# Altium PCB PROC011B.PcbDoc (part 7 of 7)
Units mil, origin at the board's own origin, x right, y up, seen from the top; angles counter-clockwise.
Board outline 3304 x 2569 mil, 6 copper layers (TOP, L2-GND1, L3-GND/SIG, L4-GND/SIG, L5-GND2, BOTTOM), stack 55.77 mil thick; 376 components, 289 nets, 1284 pads, 1755 vias.
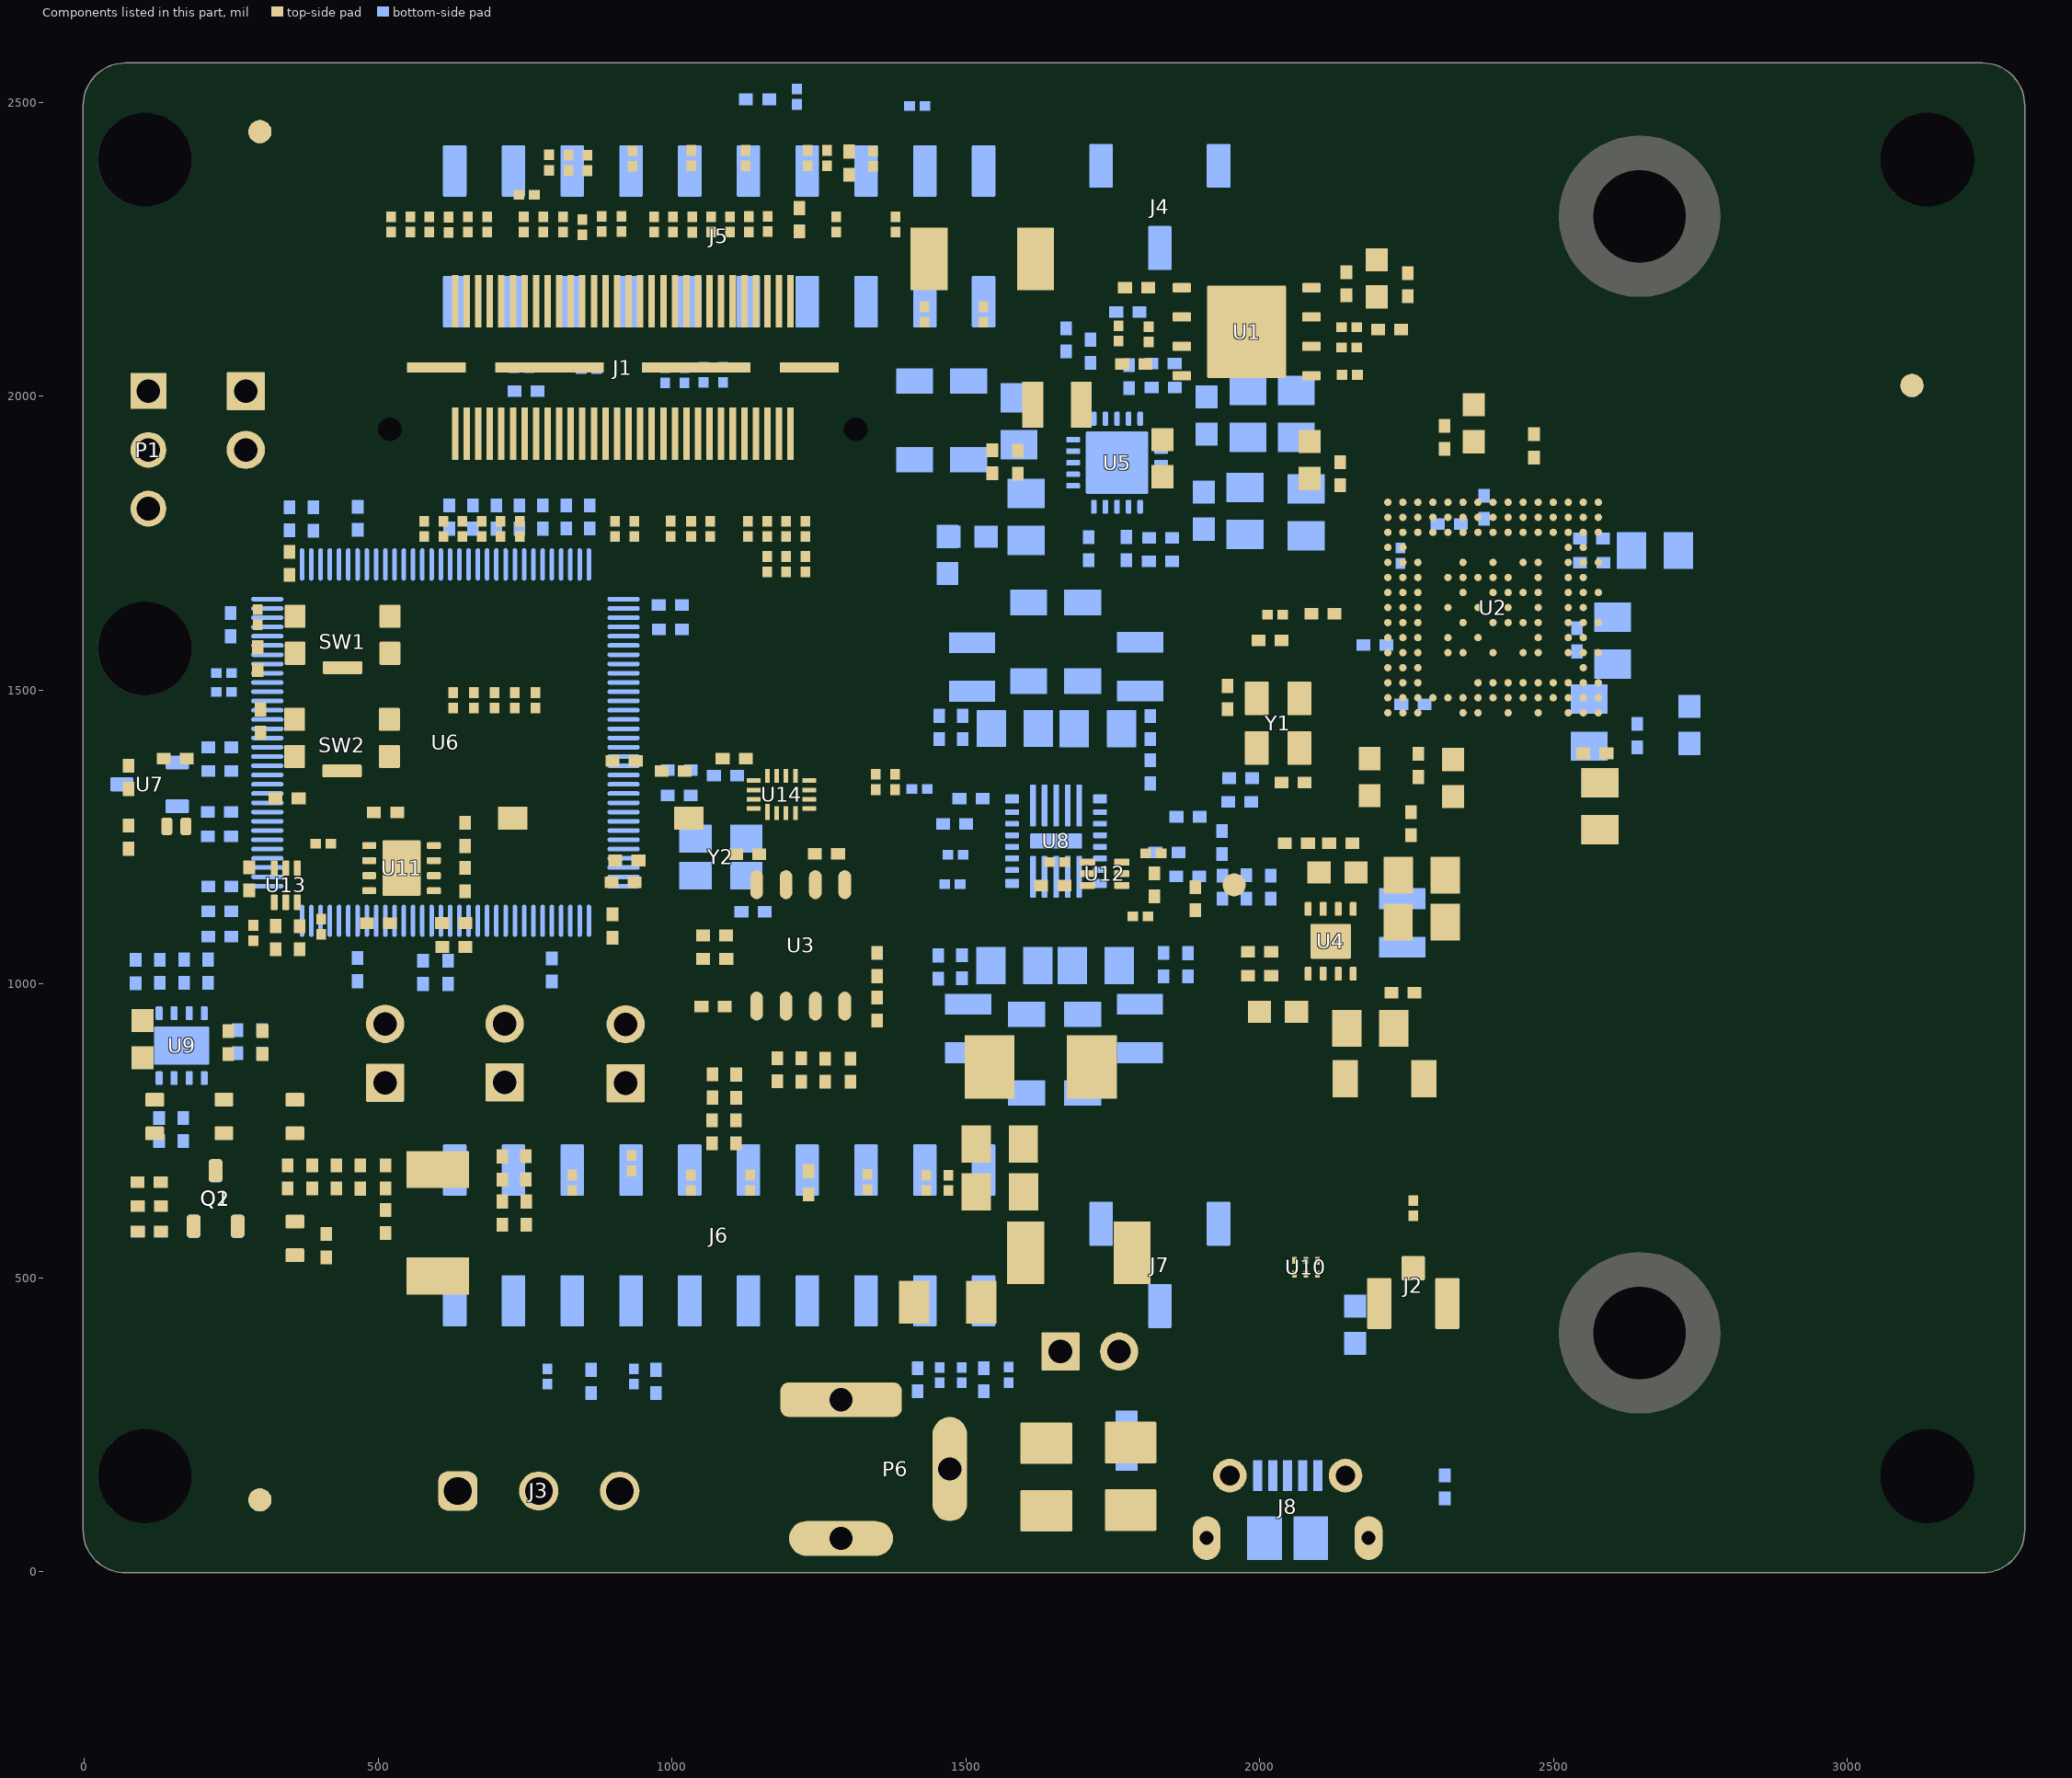
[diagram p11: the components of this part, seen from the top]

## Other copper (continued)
L4-GND/SIG:
  pour cut-out: 707.04,2233.8 707.04,2229.04 706.88,2228.89 707.03,2228.74 720.77,2228.74 720.77,2233.49 720.46,2233.8
  pour cut-out: 1164.04,659.3 1164.04,651.25 1166,649.29 1173.35,649.29 1176.16,652.1 1176.16,659.12 1174.68,660.6 1165.34,660.6
  pour cut-out: 1417.37,839.9 1417.1,839.88 1415.6,841.28 1415.48,841.41 1415.37,841.54 1415.27,841.68 1415.18,841.83 1415.11,841.99 1415.05,842.16 1415.01,842.33 1414.98,842.5 1414.96,842.67 1414.96,842.74 1414.96,1169.26 1414.97,1169.43 1414.99,1169.61 1415.03,1169.78 1415.08,1169.94 1415.15,1170.1 1415.23,1170.26 1415.33,1170.41 1415.43,1170.54 1415.55,1170.67 1415.68,1170.79 1415.82,1170.89 1415.97,1170.99 1417,1171.59 1417.15,1171.67 1417.32,1171.74 1417.48,1171.79 1417.65,1171.83 1417.82,1171.85 1418,1171.86 1418.17,1171.85 1418.35,1171.83 1418.52,1171.79 1418.68,1171.74 1418.84,1171.67 1418.9,1171.64 1419.27,1171.46 1419.27,1192.66 1419.28,1192.83 1419.3,1193.01 1419.34,1193.18 1419.39,1193.34 1419.46,1193.51 1419.54,1193.66 1419.63,1193.81 1419.74,1193.95 1419.86,1194.07 1419.98,1194.19 1420,1194.2 1422.74,1196.45 1423.6,1196.67 1424.05,1196.58 1424.05,1196.57 1425.56,1196.33 1425.84,1196.31 1426.01,1196.29 1426.18,1196.25 1426.35,1196.19 1426.51,1196.13 1426.66,1196.04 1426.81,1195.95 1426.95,1195.84 1427.08,1195.72 1427.19,1195.59 1427.3,1195.45 1427.39,1195.31 1427.47,1195.15 1427.53,1194.99 1427.59,1194.82 1427.62,1194.65 1427.64,1194.48 1427.65,1194.32 1427.65,825.7 1426.66,824.57 1425.91,824.47 1424.43,824.21 1424.19,824.16 1423.73,824.05 1422.85,824.24 1420.02,826.48 1419.89,826.59 1419.77,826.72 1419.66,826.86 1419.56,827 1419.48,827.15 1419.41,827.31 1419.35,827.48 1419.31,827.65 1419.28,827.82 1419.27,827.99 1419.27,828.05 1419.27,842.69 1419.26,842.52 1419.24,842.34 1419.2,842.17 1419.15,842.01 1419.08,841.85 1419,841.69 1418.9,841.54 1418.8,841.41 1418.72,841.32 1417.37,839.9
  pour cut-out: 1421.27,633.02 1421.27,633.01 1421.1,633.02 1420.92,633.04 1420.75,633.08 1420.59,633.13 1420.42,633.2 1420.27,633.28 1420.12,633.37 1419.98,633.48 1419.86,633.6 1419.74,633.72 1419.63,633.86 1419.54,634.01 1419.46,634.16 1419.39,634.33 1419.34,634.49 1419.3,634.66 1419.28,634.84 1419.27,635.01 1419.27,786.75 1419.28,786.92 1419.3,787.1 1419.34,787.27 1419.39,787.43 1419.45,787.6 1419.53,787.75 1419.63,787.9 1419.73,788.04 1419.85,788.17 1419.98,788.29 1420.02,788.32 1422.85,790.56 1423.73,790.75 1424.19,790.64 1425.67,790.36 1425.91,790.33 1426.66,790.23 1427.65,789.1 1427.65,660.69 1427.66,660.52 1427.68,660.34 1427.72,660.17 1427.77,660.01 1427.84,659.84 1427.92,659.69 1428.01,659.54 1428.12,659.4 1428.24,659.28 1428.24,659.27 1451.09,636.43 1451.21,636.3 1451.31,636.16 1451.41,636.01 1451.49,635.86 1451.55,635.7 1451.6,635.53 1451.64,635.36 1451.66,635.19 1451.67,635.01 1451.66,634.84 1451.64,634.67 1451.6,634.5 1451.55,634.33 1451.52,634.25 1451.29,633.68 1450.29,633.02 1421.27,633.02
  pour cut-out: 2548.83,2011.37 2547.8,2011.32 2547.33,2011.56 2545.96,2012.18 2544.54,2012.68 2543.09,2013.05 2541.61,2013.3 2540.11,2013.41 2538.61,2013.39 2537.11,2013.25 2535.63,2012.97 2535.07,2012.83 2534.55,2012.69 2533.53,2012.96 2509.05,2037.43 2508.93,2037.56 2508.83,2037.7 2508.73,2037.85 2508.65,2038 2508.59,2038.16 2508.54,2038.33 2508.5,2038.5 2508.48,2038.67 2508.47,2038.85 2508.47,2101.5 2508.48,2101.67 2508.5,2101.85 2508.54,2102.02 2508.59,2102.18 2508.66,2102.34 2508.74,2102.5 2508.84,2102.65 2508.94,2102.78 2509.06,2102.91 2509.19,2103.03 2509.33,2103.13 2509.48,2103.23 2509.63,2103.31 2509.7,2103.34 2510.27,2103.57 2511.44,2103.34 2552.55,2062.23 2552.67,2062.1 2552.77,2061.96 2552.87,2061.81 2552.95,2061.66 2553.01,2061.5 2553.06,2061.33 2553.1,2061.16 2553.12,2060.99 2553.13,2060.82 2553.13,2015.13 2553.12,2014.96 2553.1,2014.78 2553.06,2014.61 2553.01,2014.45 2552.94,2014.28 2552.86,2014.13 2552.77,2013.98 2552.66,2013.84 2552.54,2013.72 2552.42,2013.6 2552.28,2013.49 2552.18,2013.43 2548.83,2011.37
  pour cut-out: 2552.18,1978.97 2552.33,1978.87 2552.46,1978.76 2552.59,1978.64 2552.7,1978.51 2552.8,1978.37 2552.89,1978.22 2552.97,1978.06 2553.03,1977.9 2553.08,1977.73 2553.11,1977.56 2553.13,1977.39 2553.13,1977.27 2553.13,1936.26 2553.12,1936.09 2553.1,1935.91 2553.06,1935.74 2553.01,1935.58 2552.94,1935.41 2552.86,1935.26 2552.77,1935.11 2552.66,1934.97 2552.54,1934.85 2552.42,1934.73 2552.39,1934.71 2549.63,1932.47 2548.75,1932.25 2548.31,1932.35 2546.83,1932.6 2545.33,1932.71 2543.83,1932.69 2542.33,1932.55 2540.86,1932.27 2539.41,1931.87 2538.27,1931.45 2537.8,1931.26 2536.82,1931.37 2533.65,1933.5 2533.51,1933.61 2533.38,1933.72 2533.26,1933.85 2533.15,1933.98 2533.06,1934.13 2532.97,1934.28 2532.9,1934.44 2532.85,1934.61 2532.81,1934.78 2532.78,1934.95 2532.77,1935.13 2532.77,1935.15 2532.77,1975.16 2532.78,1975.33 2532.8,1975.51 2532.84,1975.68 2532.89,1975.84 2532.95,1976.01 2533.03,1976.16 2533.13,1976.31 2533.23,1976.45 2533.35,1976.58 2533.45,1976.67 2536.04,1978.94 2536.86,1979.19 2537.29,1979.13 2538.79,1979 2540.29,1979 2541.79,1979.13 2543.26,1979.39 2544.72,1979.77 2546.13,1980.29 2547.33,1980.84 2547.8,1981.08 2548.83,1981.03 2552.18,1978.97
  pour cut-out: 1735.73,1667.3 1735.73,1581.11 1735.74,1580.94 1735.76,1580.76 1735.8,1580.59 1735.85,1580.43 1735.92,1580.26 1736,1580.11 1736.09,1579.96 1736.2,1579.82 1736.32,1579.7 1736.32,1579.69 1755.09,1560.93 1755.21,1560.8 1755.31,1560.66 1755.41,1560.51 1755.49,1560.36 1755.55,1560.2 1755.6,1560.03 1755.64,1559.86 1755.66,1559.69 1755.67,1559.51 1755.66,1559.34 1755.64,1559.17 1755.6,1559 1755.55,1558.83 1755.52,1558.75 1755.29,1558.18 1754.29,1557.52 1626.56,1557.52 1626.39,1557.53 1626.21,1557.55 1626.04,1557.59 1625.88,1557.64 1625.71,1557.71 1625.56,1557.79 1625.41,1557.88 1625.27,1557.99 1625.15,1558.11 1625.03,1558.23 1624.92,1558.37 1624.83,1558.52 1624.75,1558.67 1624.72,1558.75 1624.48,1559.32 1624.72,1560.49 1732.32,1668.1 1732.45,1668.22 1732.59,1668.32 1732.74,1668.42 1732.89,1668.5 1733.05,1668.56 1733.22,1668.61 1733.39,1668.65 1733.56,1668.67 1733.74,1668.68 1733.91,1668.67 1734.08,1668.65 1734.25,1668.61 1734.42,1668.56 1734.5,1668.53 1735.07,1668.29 1735.73,1667.3
  pour cut-out: 1500.85,1793.15 1501.01,1793.08 1501.16,1792.99 1501.3,1792.88 1501.43,1792.77 1501.55,1792.64 1501.66,1792.51 1501.76,1792.36 1501.84,1792.21 1501.91,1792.05 1501.97,1791.88 1502.01,1791.71 1502.04,1791.54 1502.05,1791.37 1502.05,1791.32 1502.05,1728.61 1502.04,1728.44 1502.02,1728.26 1501.98,1728.09 1501.93,1727.93 1501.86,1727.76 1501.78,1727.61 1501.69,1727.46 1501.58,1727.32 1501.46,1727.2 1501.46,1727.19 1480.93,1706.66 1480.8,1706.54 1480.66,1706.44 1480.51,1706.34 1480.36,1706.26 1480.2,1706.2 1480.03,1706.15 1479.86,1706.11 1479.69,1706.09 1479.51,1706.08 1479.34,1706.09 1479.17,1706.11 1479,1706.15 1478.83,1706.2 1478.75,1706.23 1478.18,1706.46 1477.51,1707.46 1477.51,1785.9 1477.52,1786.07 1477.54,1786.25 1477.58,1786.42 1477.63,1786.58 1477.7,1786.75 1477.78,1786.9 1477.87,1787.05 1477.98,1787.19 1478.1,1787.31 1478.18,1787.39 1480.71,1789.66 1481.51,1789.92 1481.94,1789.88 1483.44,1789.78 1484.94,1789.82 1486.43,1789.99 1487.91,1790.29 1489.35,1790.71 1490.75,1791.26 1492.09,1791.93 1493.37,1792.71 1494.58,1793.6 1495.35,1794.27 1495.8,1794.68 1496.95,1794.87 1500.85,1793.15
  pour cut-out: 1132.48,2240.73 1131.78,2239.97 1131.29,2239.8 1129.89,2239.25 1128.55,2238.58 1127.26,2237.8 1126.05,2236.91 1124.92,2235.92 1123.89,2234.83 1122.95,2233.66 1122.12,2232.41 1121.39,2231.09 1120.79,2229.72 1120.31,2228.29 1119.96,2226.83 1119.73,2225.35 1119.63,2223.85 1119.67,2222.35 1119.83,2220.86 1120.13,2219.38 1120.55,2217.94 1121.1,2216.54 1121.76,2215.2 1122.55,2213.91 1123.44,2212.7 1124.43,2211.57 1125.52,2210.54 1126.69,2209.6 1127.94,2208.77 1129.26,2208.04 1130.63,2207.44 1132.06,2206.96 1133.52,2206.61 1135,2206.38 1136.5,2206.28 1138,2206.32 1139.49,2206.48 1140.97,2206.78 1142.41,2207.2 1143.81,2207.75 1145.15,2208.42 1146.44,2209.2 1147.65,2210.09 1148.78,2211.08 1149.81,2212.17 1150.75,2213.34 1151.58,2214.59 1152.31,2215.91 1152.91,2217.28 1153.15,2217.94 1153.32,2218.43 1154.08,2219.13 1157.89,2220.01 1158.06,2220.04 1158.24,2220.06 1158.41,2220.06 1158.58,2220.05 1158.76,2220.02 1158.93,2219.98 1159.09,2219.92 1159.25,2219.85 1159.4,2219.76 1159.55,2219.66 1159.68,2219.55 1159.76,2219.48 1174.71,2204.53 1174.83,2204.4 1174.93,2204.26 1175.03,2204.12 1175.11,2203.96 1175.18,2203.8 1175.23,2203.63 1175.27,2203.46 1175.29,2203.29 1175.3,2203.12 1175.29,2202.94 1175.27,2202.77 1175.23,2202.6 1175.18,2202.43 1175.15,2202.35 1174.91,2201.78 1173.92,2201.12 1088.25,2201.12 1088.08,2201.13 1087.9,2201.15 1087.73,2201.19 1087.57,2201.24 1087.41,2201.31 1087.25,2201.39 1087.1,2201.49 1086.97,2201.59 1086.84,2201.71 1086.72,2201.84 1086.62,2201.98 1086.52,2202.13 1086.44,2202.28 1086.41,2202.35 1086.18,2202.92 1086.41,2204.09 1124.53,2242.22 1125.56,2243.35 1126.49,2244.56 1127.32,2245.84 1128.02,2247.2 1128.09,2247.33 1128.24,2247.66 1128.49,2247.92 1128.62,2248.04 1128.76,2248.14 1128.9,2248.24 1129.06,2248.32 1129.22,2248.39 1129.39,2248.44 1129.56,2248.48 1129.73,2248.5 1129.9,2248.51 1130.08,2248.5 1130.25,2248.48 1130.42,2248.44 1130.59,2248.39 1130.75,2248.33 1130.9,2248.25 1131.05,2248.15 1131.19,2248.05 1131.32,2247.93 1131.32,2247.92 1132.83,2246.41 1132.95,2246.28 1133.05,2246.14 1133.15,2245.99 1133.23,2245.84 1133.29,2245.68 1133.34,2245.51 1133.38,2245.34 1133.4,2245.17 1133.41,2244.99 1133.4,2244.82 1133.38,2244.65 1133.36,2244.54 1132.48,2240.73
  pour cut-out: 1046.07,2214.12 927.55,2214.12 927.38,2214.13 927.2,2214.15 927.03,2214.19 926.87,2214.24 926.71,2214.31 926.55,2214.39 926.4,2214.49 926.27,2214.59 926.14,2214.71 926.02,2214.84 925.92,2214.98 925.82,2215.13 925.74,2215.28 925.71,2215.35 925.48,2215.92 925.71,2217.09 971.72,2263.1 971.85,2263.22 971.99,2263.32 972.14,2263.42 972.29,2263.5 972.45,2263.56 972.62,2263.61 972.79,2263.65 972.96,2263.67 973.13,2263.68 1051.78,2263.68 1051.95,2263.67 1052.13,2263.65 1052.3,2263.61 1052.46,2263.56 1052.63,2263.5 1052.78,2263.42 1052.93,2263.32 1053.07,2263.22 1053.2,2263.1 1053.32,2262.97 1053.42,2262.84 1055.58,2259.76 1055.71,2258.79 1055.55,2258.33 1055.1,2256.9 1054.78,2255.43 1054.59,2253.94 1054.53,2252.44 1054.6,2250.94 1054.8,2249.45 1055.13,2247.98 1055.59,2246.55 1056.17,2245.17 1056.87,2243.84 1057.68,2242.57 1058.6,2241.38 1059.62,2240.28 1060.73,2239.27 1061.92,2238.36 1063.19,2237.56 1063.6,2237.32 1064.12,2236.55 1064.6,2232.93 1064.62,2232.76 1064.62,2232.58 1064.6,2232.41 1064.57,2232.24 1064.53,2232.07 1064.47,2231.9 1064.39,2231.75 1064.31,2231.59 1064.21,2231.45 1064.09,2231.32 1064.04,2231.26 1047.48,2214.7 1047.35,2214.58 1047.21,2214.48 1047.06,2214.38 1046.91,2214.3 1046.75,2214.24 1046.58,2214.19 1046.41,2214.15 1046.24,2214.13 1046.07,2214.12
  pour cut-out: 1393.52,1312.55 1392.95,1312.31 1391.77,1312.55 1389.85,1314.47 1389.73,1314.6 1389.63,1314.74 1389.53,1314.89 1389.45,1315.04 1389.39,1315.2 1389.34,1315.37 1389.3,1315.54 1389.28,1315.71 1389.27,1315.88 1389.27,1451.36 1389.28,1451.53 1389.3,1451.71 1389.34,1451.88 1389.39,1452.04 1389.46,1452.21 1389.54,1452.36 1389.63,1452.51 1389.74,1452.65 1389.86,1452.77 1389.98,1452.89 1390.12,1453 1390.27,1453.09 1390.42,1453.17 1390.59,1453.24 1390.75,1453.29 1390.84,1453.31 1391.56,1453.47 1391.56,1453.46 1391.73,1453.49 1391.91,1453.51 1392.08,1453.51 1392.26,1453.49 1392.43,1453.46 1392.6,1453.42 1392.76,1453.36 1392.92,1453.28 1393.07,1453.19 1393.21,1453.09 1393.34,1452.98 1393.47,1452.86 1393.58,1452.72 1393.68,1452.58 1393.75,1452.46 1394.45,1451.23 1394.54,1451.08 1394.61,1450.92 1394.67,1450.75 1394.71,1450.59 1394.73,1450.46 1394.73,1314.11 1394.7,1313.94 1394.65,1313.77 1394.59,1313.61 1394.51,1313.45 1394.42,1313.3 1394.32,1313.16 1394.2,1313.03 1394.08,1312.91 1393.94,1312.8 1393.8,1312.7 1393.65,1312.61 1393.52,1312.55
  pour cut-out: 2438.84,2251.79 2439.05,2251.51 2439.23,2251.21 2439.39,2250.9 2439.52,2250.58 2439.62,2250.24 2439.69,2249.9 2439.73,2249.55 2439.74,2249.21 2439.72,2248.86 2439.67,2248.51 2439.59,2248.17 2439.48,2247.84 2439.34,2247.52 2439.18,2247.21 2438.99,2246.92 2438.77,2246.65 2438.53,2246.39 2438.5,2246.36 2437.13,2244.94 2435.9,2243.41 2434.8,2241.78 2433.84,2240.05 2433.04,2238.26 2432.4,2236.39 2431.93,2234.48 2431.62,2232.54 2431.49,2230.57 2431.52,2228.6 2431.73,2226.65 2432.11,2224.71 2432.65,2222.82 2433.36,2220.98 2434.22,2219.21 2435.24,2217.53 2436.12,2216.29 2436.53,2215.75 2436.53,2208.92 2425.98,2208.92 2424.4,2210.09 2422.72,2211.12 2420.96,2212.01 2419.13,2212.73 2417.24,2213.29 2415.31,2213.69 2413.36,2213.91 2412.67,2213.95 2412.32,2213.98 2411.98,2214.04 2411.64,2214.13 2411.31,2214.25 2411,2214.4 2410.69,2214.57 2410.41,2214.77 2410.14,2214.99 2409.89,2215.24 2409.67,2215.5 2409.46,2215.79 2409.29,2216.09 2409.14,2216.41 2409.02,2216.73 2408.93,2217.07 2408.87,2217.41 2408.83,2217.76 2408.83,2218.11 2408.86,2218.46 2408.92,2218.8 2409.01,2219.14 2409.13,2219.47 2409.28,2219.78 2409.45,2220.09 2409.65,2220.37 2409.87,2220.64 2411.13,2222.15 2412.25,2223.77 2413.22,2225.48 2414.05,2227.27 2414.71,2229.13 2415.21,2231.03 2415.54,2232.97 2415.7,2234.93 2415.69,2236.9 2415.51,2238.86 2415.16,2240.8 2414.64,2242.7 2413.96,2244.55 2413.11,2246.33 2412.12,2248.03 2410.98,2249.63 2409.71,2251.14 2409.27,2251.6 2409.03,2251.86 2408.82,2252.13 2408.64,2252.43 2408.48,2252.74 2408.35,2253.07 2408.25,2253.4 2408.17,2253.74 2408.13,2254.09 2408.12,2254.44 2408.14,2254.78 2408.19,2255.13 2408.27,2255.47 2408.37,2255.8 2408.51,2256.12 2408.67,2256.43 2408.86,2256.72 2409.08,2257 2409.32,2257.25 2409.58,2257.49 2409.85,2257.7 2410.15,2257.88 2410.46,2258.04 2410.79,2258.17 2411.12,2258.27 2411.46,2258.35 2411.72,2258.38 2432.24,2258.38 2438.84,2251.79
  pour cut-out: 2260.33,1583.77 2219.23,1583.77 2218.88,1583.82 2218.54,1583.9 2218.21,1584.01 2217.89,1584.15 2217.59,1584.31 2217.29,1584.5 2217.02,1584.72 2216.77,1584.96 2216.53,1585.22 2216.32,1585.5 2216.14,1585.79 2215.98,1586.11 2215.85,1586.43 2215.75,1586.76 2215.68,1587.11 2215.64,1587.45 2215.63,1587.8 2215.65,1588.15 2215.7,1588.5 2215.78,1588.83 2215.89,1589.17 2216.03,1589.49 2216.19,1589.79 2216.38,1590.09 2216.6,1590.36 2216.8,1590.58 2257.92,1631.7 2258.18,1631.93 2258.46,1632.15 2258.75,1632.33 2259.06,1632.5 2259.38,1632.63 2259.71,1632.73 2260.06,1632.81 2260.4,1632.85 2260.75,1632.87 2261.1,1632.85 2261.44,1632.81 2261.79,1632.73 2262.12,1632.63 2262.44,1632.5 2262.75,1632.33 2263.04,1632.15 2263.32,1631.93 2263.58,1631.7 2263.81,1631.44 2264.03,1631.16 2264.21,1630.87 2264.38,1630.56 2264.51,1630.24 2264.61,1629.91 2264.69,1629.56 2264.73,1629.27 2264.73,1623.99 2275.07,1613.66 2275.28,1613.38 2275.46,1613.08 2275.62,1612.77 2275.75,1612.45 2275.85,1612.11 2275.92,1611.77 2275.96,1611.42 2275.97,1611.08 2275.95,1610.73 2275.9,1610.38 2275.82,1610.04 2275.71,1609.71 2275.57,1609.39 2275.41,1609.08 2275.21,1608.79 2275,1608.52 2274.76,1608.26 2274.5,1608.03 2274.28,1607.86 2272.59,1606.54 2271.02,1605.08 2269.58,1603.5 2268.29,1601.79 2267.15,1599.97 2266.17,1598.06 2265.36,1596.08 2264.73,1594.03 2264.28,1591.93 2264.01,1589.81 2263.93,1587.76 2263.92,1587.41 2263.87,1587.07 2263.8,1586.72 2263.69,1586.39 2263.56,1586.07 2263.4,1585.76 2263.21,1585.46 2263,1585.19 2262.77,1584.93 2262.51,1584.69 2262.23,1584.48 2261.94,1584.29 2261.63,1584.13 2261.31,1583.99 2260.97,1583.89 2260.63,1583.81 2260.33,1583.77
  text "LAYER-4 GND/SIGNAL" at -1322.23,-1041.27 h75
L5-GND2:
  pour cut-out: 1164.04,659.3 1164.04,650 1174.06,650 1176.16,652.1 1176.16,660.58 1174.24,662.5 1167.24,662.5
  pour cut-out: 1315.51,614.1 1310.96,609.55 1310.96,609.2 1314.76,605.4 1316.65,605.4 1320,608.75 1320,610.95 1318.45,612.5
  pour cut-out: 2135.15,523.6 2142.36,516.39 2142.36,512.5 2129.47,512.5 2123.15,518.82 2123.15,520 2123.35,519.8 2129.75,519.8 2130.32,520.37
  pour cut-out: 2296.73,1703.89 2302.84,1710 2307.09,1710 2308.39,1708.69 2308.39,1700.47 2298.93,1691 2296.73,1693.2
  pour cut-out: 2369.81,2242.61 2376.95,2242.61 2376.89,2242.55 2376.89,2229.49 2369.75,2229.49 2369.81,2229.55
  pour cut-out: 1293.95,2337.79 1299.64,2332.1 1297.25,2332.1 1290.94,2325.79 1286.73,2330 1286.58,2330 1293.12,2336.54
  pour cut-out: 1023.95,2497.21 1030.97,2497.21 1030.97,2484.87 1031.15,2484.69 1024.13,2484.69 1024.13,2497.03
  text "LAYER-5 GND2" at -1308.33,-1043.01 h75
BOTTOM:
  pour cut-out: 2260.35,1453.3 2251.95,1453.3 2251.95,1497.4 2260.35,1497.4 2260.35,1453.3
  pour cut-out: 2195.35,1562.4 2187.45,1562.4 2187.45,1598.3 2195.35,1598.3 2195.35,1562.4
  pour cut-out: 2331.95,1769.3 2323.45,1769.3 2323.45,1800.7 2331.95,1800.7 2331.95,1769.3
  pour cut-out: 2191.05,411.4 2178.35,411.4 2177.75,412 2177.75,425.3 2180.35,427.9 2190.55,427.9 2191.35,427.1 2191.35,411.7 2191.05,411.4
  pour cut-out: 2298.65,1079.5 2285.75,1079.5 2281.85,1083.4 2281.85,1113.5 2295.25,1126.9 2300.37,1126.9 2301.08,1126.19 2301.08,1081.93 2298.65,1079.5
  pour cut-out: 2176.54,1079.6 2176.53,1079.59 2176.53,1106.48 2179.45,1109.4 2200.35,1109.4 2203.25,1106.5 2203.25,1094.9 2190.35,1082 2180.75,1082 2178.35,1079.6 2176.54,1079.6
  pour cut-out: 2611.75,1289.5 2537.75,1289.5 2537.75,1301.5 2611.75,1301.5 2611.75,1289.5
  pour cut-out: 2129.4,413 2129.05,412.96 2128.7,412.95 2128.36,412.97 2128.01,413.02 2127.67,413.1 2127.34,413.21 2127.02,413.35 2126.71,413.52 2126.42,413.71 2126.15,413.93 2125.9,414.17 2125.66,414.43 2125.46,414.71 2125.27,415.01 2125.12,415.32 2124.99,415.64 2124.89,415.98 2124.82,416.32 2124.78,416.67 2124.77,416.94 2124.77,483.22 2124.78,483.39 2124.8,483.57 2124.84,483.74 2124.89,483.9 2124.96,484.07 2125.04,484.22 2125.13,484.37 2125.24,484.51 2125.36,484.63 2125.48,484.75 2125.62,484.86 2125.77,484.95 2125.92,485.03 2126.09,485.1 2126.25,485.15 2126.42,485.19 2126.6,485.21 2126.77,485.22 2126.94,485.21 2127.12,485.19 2127.29,485.15 2127.45,485.1 2127.62,485.03 2127.77,484.95 2127.92,484.86 2127.99,484.8 2129.36,483.83 2130.52,483.14 2130.77,483.01 2134.48,479.29 2134.03,478.22 2134.03,424.78 2146.99,424.78 2146.99,415.22 2133.59,415.22 2133.41,414.92 2133.22,414.63 2132.99,414.36 2132.75,414.11 2132.48,413.89 2132.2,413.69 2131.9,413.51 2131.58,413.36 2131.25,413.24 2130.92,413.15 2130.57,413.09 2130.22,413.05 2130.03,413.05 2129.68,413.03 2129.4,413
  pour cut-out: 2098.73,307.02 2090.27,307.02 2090.27,374.94 2127.21,411.88 2127.46,412.12 2127.74,412.33 2128.04,412.52 2128.35,412.68 2128.67,412.81 2129,412.92 2129.34,412.99 2129.69,413.04 2130.04,413.05 2130.39,413.03 2130.73,412.99 2131.07,412.91 2131.4,412.81 2131.73,412.67 2132.04,412.51 2132.33,412.32 2132.61,412.11 2132.86,411.87 2133.1,411.62 2133.31,411.34 2133.5,411.04 2133.66,410.73 2133.79,410.41 2133.9,410.08 2133.97,409.74 2134.02,409.39 2134.03,409.05 2134.03,378.19 2098.73,342.89 2098.73,307.02
  pour cut-out: 2307.71,1639.35 2314.21,1632.84 2314.21,1630.22 2304.92,1620.92 2298.68,1627.17 2299.61,1627.17 2308.12,1635.67 2308.12,1640.5
  text "BOTTOM" at -1318.46,-1042.03 h75

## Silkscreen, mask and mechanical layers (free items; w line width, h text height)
Top Overlay:
  lines w10: 176.28,1919.69 179.6,1919.69 193.53,1905.76 193.53,1794.32 187.71,1800.14 200.17,1800.14 194.35,1794.32
  lines w30: 1378.75,904.5 1378.75,818 1459.85,818 ; 1378.75,1094.5 1378.75,1274.5 ; 1382.75,1830 1382.75,2242 ; 1700.75,2258 2146.75,2258 ; 1786.25,818 2088.75,818 ; 2268.75,2258 2474.75,2258 ; 2770.75,1968 2770.75,2182
  text "HD_CONN" at 467.92,2015.1 h30 r90
  text "VPP_1P7" at 381.32,1862.65 h30 r90
  text "1642-EVM" at 813.79,1694.33 h30
  text "GND" at 209.45,1680.5 h30 r90
  text "PROC011" at 775,1637.52 h30
  text "REV B" at 969.45,1635.95 h30
  text "GPIO1" at 620.25,1543 h30 r90
  text "ON" at 1079.14,1311 h30 r90
  text "NRST" at 615.01,1295.07 h30 r90
  text "SPI" at 709,1164 h30 r90
  text "CAN" at 1079.14,1153 h30 r90
  text "SOP0" at 1025.49,883.72 h30 r90
  text "5V" at 385.25,854.5 h30 r90
  text "NERR_OUT" at 211.42,848.5 h30 r90
  text "SOP1" at 821.68,840.86 h30 r90
  text "SOP2" at 615.55,835.13 h30 r90
  text "NRST" at 404.16,399.06 h30 r90
  text "5V_IN" at 1194.75,354 h30 r90
  text "GND" at 790.25,294 h30 r90
  text "CAN_L" at 1066.42,227.5 h30 r90
  text "CAN_H" at 542.42,226.5 h30 r90
  text "USB" at 2011.93,198.27 h30
  text "SILKSCREEN TOP" at -1339.97,-1029.03 h60
Bottom Overlay:
  drawing of 8192 lines, arcs and shapes, not listed
  text "GND" at 1745.25,2556 h30 r90
  text "GND" at 1845.25,2556 h30 r90
  text "3V3" at 1943.47,2549.66 h30 r90
  text "GND" at 596.45,2529.6 h30 r90
  text "20" at 1634.19,2423.68 h30 r90
  text "2" at 552.36,2404.47 h30 r90
  text "19" at 1638.64,2210.67 h30 r90
  text "1" at 544.91,2180.78 h30 r90
  text "P1" at 132.79,2073.5 h30
  text "P7" at 396.41,2020 h30
  text "P4" at 955.85,1005.8 h30
  text "P3" at 537.9,1001.27 h30
  text "P2" at 736.23,1000.15 h30
  text "GND" at 790.25,886 h30 r90
  text "GND" at 1845.25,776 h30 r90
  text "GND" at 1735.25,771 h30 r90
  text "20" at 1641.82,729.19 h30 r90
  text "2" at 553.44,705.94 h30 r90
  text "19" at 1656.65,524.84 h30 r90
  text "1" at 545.99,482.25 h30 r90
  text "P6" at 1317.41,338.79 h30
  text "P5" at 1877.7,327.72 h30
  text "J3" at 538.18,135.69 h30
  text "SILKSCREEN BOTTOM" at -1330.97,-1032.41 h75
Top Paste:
  text "SOLDERPASTE TOP" at -1322.76,-1029.77 h75
Bottom Paste:
  text "SOLDERPASTE BOTTOM" at -1315.43,-1031.21 h75
Top Solder:
  text "SOLDERMASK TOP" at -1325.23,-1033.37 h75
Bottom Solder:
  text "SOLDERMASK BOTTOM" at -1292.25,-1013.98 h75
OUTLINE:
  lines w4: 0,70 ccw(c70,70) 70,0 3230,0 ccw(c3230,70) 3300,70 3300,2495 ccw(c3230,2495) 3230,2565 70,2565 ccw(c70,2495) 0,2495 0,70
Board Dimensions:
  text "AT 4 PLACES" at -810,-280 h75
Mechanical 5 Ass top:
  lines w6: 163,2270 163,2286 174,2297 355,2297 405,2247 741,2247 747,2253 747,2256 ; 355.14,2202 420,2202 435,2217 897.05,2217 912,2231.95 912,2254 ; 974,2330 974,2349.96 985.04,2361 1276.02,2361 1291.02,2346 1361,2346 1376,2361 1376,2381 1391,2396 ; 1162.65,2337 1162.65,2337.65 1171,2346 1256.78,2346 1269.78,2333 1574,2333 1604,2363 1604,2371 ; 2111,2139 2111,2127.39 2113.39,2125
  lines w10: -2151.07,-1099.34 4448.93,-1099.34 ; -2151.07,-896 4450.93,-896 ; -2151.07,-692.67 -2151.07,-1302.67 1853.93,-1302.67 4450.93,-1302.67 4450.93,-692.67 -2150.57,-692.67 -2150.57,-1302.67 -575.07,-1302.67 ; 313.93,-1302.67 313.93,-692.67 ; 1580.93,-896 1580.93,-692.67 ; 2420.93,-896 2420.93,-692.67 ; 3042.93,-1309.17 3042.93,-1106.34
  text "COMPONENTS MARKED 'DNP' SHOULD NOT BE POPULATED." at -1592.26,2897.89 h60
  text "ASSEMBLY VARIANT:" at -1592.76,2782.39 h60
  text ".VariantName" at -556.76,2782.39 h60
  text "PCB VIEWED FROM TOP SIDE" at -2087.57,-824.84 h60
  text "BOARD #:" at 388.93,-824.84 h60
  text ".PRJ_Number" at 934.43,-824.84 h60
  text "REV:" at 1778.93,-824.84 h60
  text ".PCB_Rev" at 2070.43,-824.84 h60
  text "SVN REV:" at 2616.93,-824.84 h60
  text ".VersionControl_RevNumber" at 3122.93,-824.84 h60
  text "Assembly TOP" at -1818.81,-1016.17 h60
  text "TID #:" at 388.93,-1028.17 h60
  text ".TID" at 934.43,-1028.17 h60
  text "PLOT NAME =" at -2087.57,-1233.51 h60
  text ".plot_File_Name" at -1282.07,-1233.51 h35
  text "GENERATED    :" at 390.93,-1233.51 h60
  text ".Print_Date" at 1260.43,-1233.51 h60
  text ".Print_Time" at 1989.43,-1233.51 h60
  text "TEXAS INSTRUMENTS" at 3253.93,-1233.51 h60
Mechanical 6 Ass bot:
  lines w10: -2151.07,-896 4450.93,-896 ; -2149.07,-1099.34 4450.93,-1099.34 ; -743.07,-1309.17 -743.07,-1106.34 ; -121.07,-896 -121.07,-692.67 ; 718.93,-896 718.93,-692.67 ; 1985.93,-1302.67 1985.93,-692.67 ; 2874.93,-1302.67 4450.43,-1302.67 4450.43,-692.67 -2151.07,-692.67 -2151.07,-1302.67 445.93,-1302.67 4450.93,-1302.67 4450.93,-692.67
  text "COMPONENTS MARKED 'DNP' SHOULD NOT BE POPULATED." at 4243.43,-486.67 h60
  text ".VariantName" at 3199.43,-602.67 h60
  text "ASSEMBLY VARIANT:" at 4238.43,-602.67 h60
  text ".VersionControl_RevNumber" at -823.07,-824.84 h60
  text "SVN REV:" at -317.07,-824.84 h60
  text ".PCB_Rev" at 229.43,-824.84 h60
  text "REV:" at 520.93,-824.84 h60
  text ".PRJ_Number" at 1365.43,-824.84 h60
  text "BOARD #:" at 1910.93,-824.84 h60
  text "PCB VIEWED FROM BOTTOM SIDE" at 4387.43,-824.84 h60
  text ".TID" at 1365.43,-1028.17 h60
  text "TID #:" at 1910.93,-1028.17 h60
  text "ASSEMBLY BOTTOM" at 4003,-1028 h60
  text "TEXAS INSTRUMENTS" at -954.07,-1233.51 h60
  text ".Print_Time" at 310.43,-1233.51 h60
  text ".Print_Date" at 1039.43,-1233.51 h60
  text "GENERATED    :" at 1908.93,-1233.51 h60
  text ".plot_File_Name" at 3581.93,-1233.51 h35
  text "PLOT NAME =" at 4387.43,-1233.51 h60
M9 Title Sheet:
  drawing of 57 lines, arcs and shapes, not listed
  text "1" at -1119.86,7866.62 h70
  text "2" at 1375.8,7866.62 h70
  text "3" at 3865.14,7866.62 h70
  text "4" at 6371.81,7866.62 h70
  text "5" at 8870.8,7866.62 h70
  text "6" at 11375.8,7866.62 h70
  text "A" at -2276.2,6723.62 h70
  text "A" at 12523.8,6723.62 h70
  text "B" at -2276.2,4343.62 h70
  text "B" at 12523.8,4343.62 h70
  text "C" at -2276.2,1968.62 h70
  text "C" at 12523.8,1968.62 h70
  text "PROJECT TITLE:" at 9483.8,107.62 h45
  text ".PRJ_Title" at 9533.8,-25.71 h50
  text "DESIGNED FOR:" at 9483.8,-193.38 h45
  text ".PRJ_Customer" at 9533.8,-333.38 h70
  text "D" at -2276.2,-401.38 h70
  text "D" at 12523.8,-401.38 h70
  text "FILE NAME:" at 9483.8,-493.38 h45
  text ".PCB_File_Name_No_Path" at 9533.8,-613.38 h70
  text "Texas Instruments (TI) and/or its licensors do not warrant the accuracy or completeness of this specification" at 4514.3,-775.22 h45
  text "ENGINEER:" at 9483.8,-783.38 h45
  text "LAYOUT BY:" at 10988.8,-783.38 h45
  text "or any information contained therein. TI and/or its licensors do not warrant that this design will meet" at 4469.31,-887.88 h45
  text ".PRJ_Engineer" at 9533.8,-938.37 h70
  text ".PCB_Layout" at 11039.3,-938.37 h70
  text "the specifications, will be suitable for your application or fit for any particular purpose, or will operate in" at 4469.31,-1000.55 h45
  text "ALTIUM DESIGNER VERSION:" at 10988.8,-1093.38 h45
  text "an implementation. TI and/or its licensors do not warrant that the design is production worthy. You should" at 4469.31,-1113.21 h45
  text "completely validate and test your design implementation to confirm the system functionality for your application." at 4514.3,-1225.88 h45
  text ".print_Scale" at 9533.8,-1226.71 h70
  text ".Application_BuildNumber" at 11039.3,-1226.71 h70
  text "1" at -1119.86,-1433.38 h70
  text "2" at 1375.8,-1433.38 h70
  text "3" at 3865.14,-1433.38 h70
  text "4" at 6371.81,-1433.38 h70
  text "5" at 8870.8,-1433.38 h70
  text "6" at 11375.8,-1433.38 h70
LOGO_HOT:
  drawing of 189 lines, arcs and shapes, not listed
  text "DESIGN INFORMATION" at 10521.82,6186.29 h60
  text "MIL" at 11183,6056 h60
  text "MIN. TRACK WIDTH:" at 9877.26,6054.17 h60
  text "4" at 10973.5,6054.17 h60
  text "4" at 10965.36,5957.06 h60
  text "MIL" at 11182.26,5931 h60
  text "MIN. CLEARANCE:" at 9877.26,5930.04 h60
  text "MIL" at 11185,5807 h60
  text "MIN. VIA PAD SIZE:" at 9877.26,5805.92 h60
  text "13.77" at 10873,5798 h60
  text "0.05mm (2MIL)" at 10572.26,5676.02 h60
  text "MINIMUM ANNULAR RING" at 9548.03,5667.79 h60
  text "EXTERNAL" at 11280.26,5667.79 h60
  text "PER" at 9748.03,5557.67 h60
  text "IPC-D-275 CLASS 2 LEVEL C" at 9968.03,5557.66 h60
  text "MIL, HOLES" at 11456.26,5457.19 h60
  text "+/-" at 11063.8,5448.6 h60
  text "+/-" at 11917.8,5448.6 h60
  text "REGISTRATION TOLERANCES:" at 9548.03,5447.54 h60
  text "METAL" at 10747.8,5447.54 h60
  text "2" at 11324,5447.54 h60
  text "3" at 12157,5447.54 h60
  text "MIL" at 12273.26,5447.54 h60
  text "HOLE SIZE TOLERANCE (UNLESS OTHERWISE SPECIFIED):" at 9548.03,5349.22 h60
  text "+/-" at 11917.8,5346.35 h60
  text "3" at 12157,5345.29 h60
  text "MIL" at 12273.26,5345.29 h60
  text "MATERIAL:" at 9473.26,5207.64 h60
  text "FR-4 High Tg" at 10459.7,5079.12 h60
  text "X" at 11197.39,5075.36 h60
  text "FR-408" at 9894.26,5066.61 h60
  text "OTHER" at 11382.26,5066.61 h60
  text "REFER STACKUP" at 11710.91,5051.35 h60
  text "THICKNESS:" at 9489.68,4927.16 h60
  text "X" at 10000.66,4924.28 h60
  text "56.21 MIL (1.43mm) +/-10%" at 10100.96,4922.18 h60
  text "OTHER" at 11499.26,4915.36 h60
  text "TOLERANCE:" at 9548.03,4777.04 h60
  text "X" at 10396.26,4777.04 h60
  text "ANSI IPC-6012 TYPE 3 CLASS 2" at 10574.28,4777.04 h60
  text "OTHER +/-" at 10574.26,4632.85 h60
  text "BOW & TWIST:" at 9548.03,4487.66 h60
  text "X" at 10396.26,4487.66 h60
  text "ANSI IPC-6012 TYPE 3 CLASS 2" at 10574.28,4487.66 h60
  text "OTHER +/-" at 10574.26,4340.97 h60
  text "DRILLING:" at 9473.26,4210.35 h60
  text "NC_DRILL FILES" at 11234.26,4105.16 h60
  text "REFERENCE:" at 9548.03,4101.22 h60
  text "X" at 10205.26,4101.13 h60
  text "AS SHOWN" at 10383.26,4101.22 h60
  text "X" at 11106.26,4101.22 h60
  text "OTHER" at 11532.26,3958.97 h60
  text "PTH COPPER THICKNESS:" at 9547.71,3955.44 h60
  text "X" at 10686.94,3955.44 h60
  text "20-30 um" at 10814.94,3955.44 h60
  text "BOARD FINISH:" at 9473.26,3807.85 h60
  text "SILKSCREEN:" at 9628.48,3697.72 h60
  text "X" at 10586.26,3697.72 h60
  text "TOP" at 10703.26,3697.72 h60
  text "X" at 11096.26,3697.72 h60
  text "BOTTOM" at 11214.26,3697.72 h60
  text "SILKSCREEN COLOR:" at 9628.48,3542.53 h60
  text "X" at 10585.26,3542.53 h60
  text "WHITE" at 10703.26,3542.53 h60
  text "OTHER" at 11214.26,3542.53 h60
  text "GREEN" at 10834.26,3399.08 h60
  text "OTHER" at 11452.26,3399.08 h60
  text "X" at 11296.74,3395.1 h60
  text "RED" at 11875.95,3395.11 h60
  text "SOLDER RESIST COLOR:" at 9628.48,3392.22 h60
  text "X" at 10716.26,3244.83 h60
  text "MATTE" at 10834.26,3244.83 h60
  text "SEMI-GLOSS" at 11451.8,3244.19 h60
  text "IMMERSION GOLD (ENIG)" at 10534.26,3072.06 h60
  text "ENEPIG" at 11871.8,3064.84 h60
  text "SURFACE FINISH:" at 9473.26,3063.84 h60
  text "IMM SILVER" at 11653,2932 h60
  text "IMM. TIN/SILVER OR EQUIV" at 9802.8,2926.52 h60
  text "X" at 11058.66,2926.28 h60
  text "OTHER" at 11234.26,2922.59 h60
  text "ARRAY/PANEL:" at 9473.26,2767.21 h60
  text "CUT AND TRIM PER M1 BOARD OUTLINE" at 10534.26,2758.99 h60
  text "X" at 10355.66,2746.28 h60
  text "N.C. ROUTE" at 10534.26,2623.02 h60
  text "V. SCORE" at 11400.26,2623.02 h60
  text "CERTIFICATION:" at 9473.26,2493.89 h60
  text "MATERIALS AND WORKMANSHIP FOR ALL PCBS" at 10198.26,2493.89 h60
  text "TO MEET OR EXCEED THE REQUIREMENTS OF:" at 10198.26,2399.83 h60
  text "X" at 9835.77,2271.2 h60
  text "ANSI IPC-A-600F CLASS ->" at 9963.76,2271.2 h60
  text "X" at 11611.77,2271.2 h60
  text "2" at 11721.76,2271.2 h60
  text "1" at 11406.76,2269.7 h60
  text "3" at 12075.76,2269.7 h60
  text "X" at 10647.77,2123.51 h60
  text "RoHS" at 10775.76,2123.51 h60
  text "OTHER" at 11420.16,2123.51 h60
  text "PER ORDER" at 11817.22,2123.51 h60
  text "ALL BOARDS MUST MEET OR EXCEED UL94-V0 REQUIREMENTS." at 9500.8,1969.69 h60
  text "PCB MUST BEAR THE UL94V-0 UL REGISTERED MATERIAL ID NUMBER" at 9500.8,1853.62 h60
  text "ADDITIONAL REQUIREMENTS:" at 9473.26,1684.2 h60
  text "MICROSECTION:" at 9548.03,1577.07 h60
  text "YES" at 10453.76,1577.07 h60
  text "REQUIRED" at 11315.26,1432.74 h60
  text "BARE BOARD ELEC. TEST:" at 9548.03,1429.88 h60
  text "NONE" at 10853.76,1429.88 h60
  text "X" at 11197.26,1429.88 h60
  text "PER ORDER" at 11907.26,1429.88 h60
  text "XX MIL VIAS REQUIRE NON-CONDUCTIVE FILL AND PLANARIZE" at 9662.75,1281.5 h59
  text "XX MIL VIAS REQUIRE CONDUCTIVE FILL AND PLANARIZE" at 9648.75,1125.5 h60
  text "OUTER XX MIL TRACES REQUIRE 50 OHM SINGLE-ENDED IMPEDANCE" at 9641.75,955.5 h58
  text "OUTER XX ML TRACES REQUIRE 100 OHM DIFFERENTIAL PAIR" at 9662.75,834.5 h60
  text "IMPEDANCE CONTROL TRACES" at 9741.75,726.5 h60
M11 Gerber Information:
  lines w10: -2151.29,-1100.49 4448.71,-1100.49 ; -2151.29,-897.15 4450.71,-897.15 ; -2151.29,-693.82 -2151.29,-1303.82 1853.71,-1303.82 4450.71,-1303.82 4450.71,-693.82 -2150.79,-693.82 -2150.79,-1303.82 -575.29,-1303.82 ; 313.71,-1303.82 313.71,-693.82 ; 1580.71,-897.15 1580.71,-693.82 ; 2420.71,-897.15 2420.71,-693.82 ; 3052.83,-1282.27 3052.83,-1079.44
  text "ALL ARTWORK VIEWED FROM TOP SIDE" at -2087.79,-825.99 h60
  text "BOARD #:" at 388.71,-825.99 h60
  text ".PRJ_Number" at 934.21,-825.99 h60
  text "REV:" at 1778.71,-825.99 h60
  text ".PCB_Rev" at 2070.21,-825.99 h60
  text "SVN REV:" at 2616.71,-825.99 h60
  text ".VersionControl_RevNumber" at 3122.71,-825.99 h60
  text "LAYER NAME =" at -2087.79,-1028.81 h60
  text "TID #:" at 388.71,-1029.32 h60
  text ".TID" at 934.21,-1029.32 h60
  text ".plot_File_Name" at -1429,-1231 h50
  text "PLOT NAME =" at -2087.79,-1234.65 h60
  text "GENERATED    :" at 390.71,-1234.65 h60
  text ".Print_Date" at 1260.21,-1234.65 h60
  text ".Print_Time" at 1989.21,-1234.65 h60
  text "TEXAS INSTRUMENTS" at 3253.71,-1234.65 h60
Mechanical 12:
  drawing of 399 lines, arcs and shapes, not listed
  text "Layer" at 3775.5,7076.5 h60
  text "Name" at 4185.41,7076.5 h60
  text "Material" at 5115.16,7076.5 h60
  text "Thickness" at 5974.92,7076.5 h60
  text "Constant" at 6624.76,7076.5 h60
  text "Board Layer Stack" at 7194.62,7076.5 h60
  text "1" at 3775.5,6956.5 h60
  text "Top Overlay" at 4185.41,6956.5 h60
  text "2" at 3775.5,6836.5 h60
  text "Top Solder" at 4185.41,6836.5 h60
  text "Solder Resist" at 5115.16,6836.5 h60
  text "0.80mil" at 5974.92,6836.5 h60
  text "0" at 6624.76,6836.5 h60
  text "3" at 3775.5,6716.5 h60
  text "TOP" at 4185.41,6716.5 h60
  text "Copper" at 5115.16,6716.5 h60
  text "1.60mil" at 5974.92,6716.5 h60
  text "4" at 3775.5,6596.5 h60
  text "Dielectric1" at 4185.41,6596.5 h60
  text "RO4835 LOPRO" at 5115.16,6596.5 h60
  text "4.00mil" at 5974.92,6596.5 h60
  text "3.66" at 6624.76,6596.5 h60
  text "5" at 3775.5,6476.5 h60
  text "L2-GND1" at 4185.41,6476.5 h60
  text "Copper" at 5115.16,6476.5 h60
  text "1.40mil" at 5974.92,6476.5 h60
  text "6" at 3775.5,6356.5 h60
  text "Dielectric2" at 4185.41,6356.5 h60
  text "370HR" at 5115.16,6356.5 h60
  text "5.67mil" at 5974.92,6356.5 h60
  text "3.9" at 6624.76,6356.5 h60
  text "7" at 3775.5,6236.5 h60
  text "L3-GND/SIG" at 4185.41,6236.5 h60
  text "Copper" at 5115.16,6236.5 h60
  text "1.20mil" at 5974.92,6236.5 h60
  text "8" at 3775.5,6116.5 h60
  text "Dielectric3" at 4185.41,6116.5 h60
  text "370HR" at 5115.16,6116.5 h60
  text "28.00mil" at 5974.92,6116.5 h60
  text "4.36" at 6624.76,6116.5 h60
  text "9" at 3775.5,5996.5 h60
  text "L4-GND/SIG" at 4185.41,5996.5 h60
  text "Copper" at 5115.16,5996.5 h60
  text "1.20mil" at 5974.92,5996.5 h60
  text "10" at 3775.5,5876.5 h60
  text "Dielectric4" at 4185.41,5876.5 h60
  text "370HR" at 5115.16,5876.5 h60
  text "5.90mil" at 5974.92,5876.5 h60
  text "3.9" at 6624.76,5876.5 h60
  text "11" at 3775.5,5756.5 h60
  text "L5-GND2" at 4185.41,5756.5 h60
  text "Copper" at 5115.16,5756.5 h60
  text "1.20mil" at 5974.92,5756.5 h60
  text "12" at 3775.5,5636.5 h60
  text "Dielectric5" at 4185.41,5636.5 h60
  text "370HR" at 5115.16,5636.5 h60
  text "4.00mil" at 5974.92,5636.5 h60
  text "4.26" at 6624.76,5636.5 h60
  text "13" at 3775.5,5516.5 h60
  text "BOTTOM" at 4185.41,5516.5 h60
  text "Copper" at 5115.16,5516.5 h60
  text "1.60mil" at 5974.92,5516.5 h60
  text "14" at 3775.5,5396.5 h60
  text "Bottom Solder" at 4185.41,5396.5 h60
  text "Solder Resist" at 5115.16,5396.5 h60
  text "0.80mil" at 5974.92,5396.5 h60
  text "0" at 6624.76,5396.5 h60
  text "15" at 3775.5,5276.5 h60
  text "Bottom Overlay" at 4185.41,5276.5 h60
Mechanical 14:
  text "NOTES: UNLESS OTHERWISE SPECIFIED." at 3982.31,2648.8 h60
  text "1. ALL VIAS ARE TENTED ON BOTH SIDES UNLESS SOLDERMASK OPENED IN GERBER." at 3986.8,2136.01 h60
  text "2. ALL VIAS ON PAD INCLUDING BGA AREA SHOULD BE FILLED WITH NON CONDUCTIVE EPOXY AND SURFACE SHOULD BE FLAT" at 3988.14,1986.34 h60
  text "BGA AREA VIAS SHOULD BE CAPPED WITH COPPER PLATING TO ENSURE FLAT SURFACE" at 4158.14,1879.34 h60
  text "REFER VIA FILL DOCUMENT TO IDENTIFY THE VIAS TO BE FILLED" at 4158.14,1775.34 h60
  text "FLATNESS TOLERANCE FOR VIA ON PADS: +0.000 /- 0.001 INCHES ON BOTH SIDES." at 4158.14,1666.34 h60
  text "3. MANUFACTURER'S IDENTIFICATION,DATECODE LETTER SHALL BE SILKSCREENED ON SOLDER SIDE" at 3974.61,1494.94 h60
  text "OF THE BOARD." at 4144.61,1381.94 h60
  text "4. TRACE WIDTH SHOULD BE ACCURATELY ETCHED. MAX TOLERANCE +/- 1 MIL" at 3974.61,1267.94 h60
  text "5. REFER STACKUP DOCUMENT FOR IMPEDANCE CONTROL TRACES ON LAYER 1." at 3960,1134.48 h60
  text "50 OHM SINGLE ENDED AND 100 OHM DIFFERENTIAL IMPEDANCE CONTROL TRACES." at 4071,1023 h60
  text "6. SOLDER MASK OPENING IS KEPT SAME SIZE AS PAD (1:1)." at 3980,876.35 h60
  text "THE MANUFACTURER IS REQUESTED TO RESIZE IT AS PER THEIR SOLDERMASK TOLERANCE EXCEPT NPTH DRILL AND FIDUCIALS." at 4090,722.46 h60
Mechanical 16:
  lines w0.16: -48930.49,-49088.31 cw(c-48930.49,-49085.55) -48933.25,-49085.55 -48933.25,-48990.08 cw(c-48930.49,-48990.08) -48930.49,-48987.32
  lines w0.79: -48810.48,-49133.52 -48810.48,-49166 -48672.68,-49166 -48672.68,-49133.52 ; -48769.14,-49166 -48769.14,-49133.52
FAB_DWG:
  circle w10: c54.13,5804.81 r27.6
  circle w10: c54.13,5432.26 r16.56
  circle w10: c54.13,5432.26 r27.6
  lines w10: 26.54,5528.85 81.73,5528.85 81.73,5584.04 26.54,5584.04 26.54,5528.85 ; 26.54,5666.83 40.34,5666.83 54.13,5653.03 67.93,5666.83 81.73,5666.83 67.93,5680.62 81.73,5694.42 67.93,5694.42 54.13,5708.22 40.34,5694.42 26.54,5694.42 40.34,5680.62 26.54,5666.83 ; 26.54,5956.58 81.73,5956.58 54.13,5901.39 26.54,5956.58 ; 26.54,6025.57 81.73,6025.57 81.73,6080.76 26.54,6080.76 26.54,6025.57 ; 26.54,6163.55 40.34,6163.55 40.34,6149.75 67.93,6149.75 67.93,6163.55 81.73,6163.55 81.73,6191.15 67.93,6191.15 67.93,6204.94 40.34,6204.94 40.34,6191.15 26.54,6191.15 26.54,6163.55 ; 26.54,6273.93 54.13,6287.73 81.73,6273.93 67.93,6301.53 81.73,6329.13 54.13,6315.33 26.54,6329.13 40.34,6301.53 26.54,6273.93 ; 26.54,6398.12 26.54,6411.91 40.34,6425.71 26.54,6439.51 26.54,6453.31 40.34,6453.31 54.13,6439.51 67.93,6453.31 81.73,6453.31 81.73,6439.51 67.93,6425.71 81.73,6411.91 81.73,6398.12 67.93,6398.12 54.13,6411.91 40.34,6398.12 26.54,6398.12 ; 26.54,6549.89 54.13,6522.3 81.73,6549.89 54.13,6577.49 26.54,6549.89 ; 26.54,6660.28 40.34,6660.28 54.13,6646.48 67.93,6660.28 81.73,6660.28 67.93,6674.07 81.73,6687.87 67.93,6687.87 54.13,6701.67 40.34,6687.87 26.54,6687.87 40.34,6674.07 26.54,6660.28 ; 26.54,6825.85 81.73,6825.85 54.13,6770.66 26.54,6825.85 ; 37.58,5539.89 70.69,5539.89 70.69,5573 37.58,5573 37.58,5539.89 ; 37.58,6665.79 45.85,6665.79 54.13,6657.52 62.41,6665.79 70.69,6665.79 62.41,6674.07 70.69,6682.35 62.41,6682.35 54.13,6690.63 45.85,6682.35 37.58,6682.35 45.85,6674.07 37.58,6665.79 ; 37.58,6814.81 70.69,6814.81 54.13,6781.7 37.58,6814.81 ; 3363.54,4118.89 3391.13,4132.69 3418.73,4118.89 3404.93,4146.49 3418.73,4174.08 3391.13,4160.29 3363.54,4174.08 3377.34,4146.49 3363.54,4118.89 ; 3374.58,4129.93 3391.13,4138.21 3407.69,4129.93 3399.41,4146.49 3407.69,4163.05 3391.13,4154.77 3374.58,4163.05 3382.85,4146.49 3374.58,4129.93
  lines w15: -23.5,6857.59 2463.94,6857.59 ; 295.66,5367.41 295.66,6981.77 ; 538.26,5367.41 538.26,6981.77 ; 1112.33,5367.41 1112.33,6981.77 ; 1686.39,5367.41 1686.39,6981.77 ; 1933.86,5367.41 1933.86,6981.77 ; 3313.5,4205.82 5583.07,4205.82 ; 3632.66,4081.64 3632.66,4330 ; 3875.26,4081.64 3875.26,4330 ; 4393.22,4081.64 4393.22,4330 ; 4805.52,4081.64 4805.52,4330 ; 5052.99,4081.64 5052.99,4330 ; -23.5,5367.41 2463.94,5367.41 2463.94,6981.77 -23.5,6981.77 -23.5,5367.41 ; 3313.5,4081.64 5583.07,4081.64 5583.07,4330 3313.5,4330 3313.5,4081.64
  text "Symbol" at 51.01,6894.84 h72
  text "Count" at 332.91,6894.84 h72
  text "Hole Size" at 575.52,6894.84 h72
  text "Hole Length" at 1149.58,6894.84 h72
  text "Plated" at 1723.64,6894.84 h72
  text "Drill Layer Pair" at 1971.11,6894.84 h72
  text "9" at 332.91,6770.66 h60
  text "7.87mil (0.200mm)" at 575.52,6770.66 h60
  text "-" at 1149.58,6770.66 h60
  text "PTH" at 1723.64,6770.66 h60
  text "TOP - BOTTOM" at 1971.11,6770.66 h60
  text "1046" at 332.91,6646.48 h60
  text "12.20mil (0.310mm)" at 575.52,6646.48 h60
  text "-" at 1149.58,6646.48 h60
  text "PTH" at 1723.64,6646.48 h60
  text "TOP - BOTTOM" at 1971.11,6646.48 h60
  text "2" at 332.91,6522.3 h60
  text "23.62mil (0.600mm)" at 575.52,6522.3 h60
  text "51.18mil (1.300mm)" at 1149.58,6522.3 h60
  text "PTH" at 1723.64,6522.3 h60
  text "TOP - BOTTOM" at 1971.11,6522.3 h60
  text "2" at 332.91,6398.12 h60
  text "33.47mil (0.850mm)" at 575.52,6398.12 h60
  text "-" at 1149.58,6398.12 h60
  text "PTH" at 1723.64,6398.12 h60
  text "TOP - BOTTOM" at 1971.11,6398.12 h60
  text "2" at 332.91,6273.93 h60
  text "39.37mil (1.000mm)" at 575.52,6273.93 h60
  text "118.11mil (3.000mm)" at 1149.58,6273.93 h60
  text "PTH" at 1723.64,6273.93 h60
  text "TOP - BOTTOM" at 1971.11,6273.93 h60
  text "1" at 332.91,6149.75 h60
  text "39.37mil (1.000mm)" at 575.52,6149.75 h60
  text "137.80mil (3.500mm)" at 1149.58,6149.75 h60
  text "PTH" at 1723.64,6149.75 h60
  text "TOP - BOTTOM" at 1971.11,6149.75 h60
  text "10" at 332.91,6025.57 h60
  text "40.00mil (1.016mm)" at 575.52,6025.57 h60
  text "-" at 1149.58,6025.57 h60
  text "PTH" at 1723.64,6025.57 h60
  text "TOP - BOTTOM" at 1971.11,6025.57 h60
  text "2" at 332.91,5901.39 h60
  text "40.16mil (1.020mm)" at 575.52,5901.39 h60
  text "-" at 1149.58,5901.39 h60
  text "NPTH" at 1723.64,5901.39 h60
  text "TOP - BOTTOM" at 1971.11,5901.39 h60
  text "3" at 332.91,5777.21 h60
  text "40.16mil (1.020mm)" at 575.52,5777.21 h60
  text "-" at 1149.58,5777.21 h60
  text "PTH" at 1723.64,5777.21 h60
  text "TOP - BOTTOM" at 1971.11,5777.21 h60
  text "3" at 332.91,5653.03 h60
  text "47.24mil (1.200mm)" at 575.52,5653.03 h60
  text "-" at 1149.58,5653.03 h60
  text "PTH" at 1723.64,5653.03 h60
  text "TOP - BOTTOM" at 1971.11,5653.03 h60
  text "2" at 332.91,5528.85 h60
  text "157.48mil (4.000mm)" at 575.52,5528.85 h60
  text "-" at 1149.58,5528.85 h60
  text "PTH" at 1723.64,5528.85 h60
  text "TOP - BOTTOM" at 1971.11,5528.85 h60
  text "5" at 332.91,5404.67 h60
  text "160.00mil (4.064mm)" at 575.52,5404.67 h60
  text "-" at 1149.58,5404.67 h60
  text "NPTH" at 1723.64,5404.67 h60
  text "TOP - BOTTOM" at 1971.11,5404.67 h60
  text "Slot definitions :" at 51.01,5317.74 h60
  text "Routed Path Length" at 460.22,5317.74 h60
  text "= Calculated from tool start centre position to tool end centre position." at 967.17,5317.74 h60
  text "Hole Length" at 460.22,5268.07 h60
  text "= Routed Path Length + Tool Size = Slot length as defined in the PCB layout" at 778.97,5268.07 h60
  text "FOR 7.87MIL DRILL +0/-7.87MIL" at 220.6,5050 h60
  text "FOR 12.20 MIL DRILL +0/-12.20MIL" at 220.52,4945.19 h60
  text "FOR PTH +/-3MIL" at 224.82,4824.79 h60
  text "FOR NPTH +/-2MIL" at 224.82,4670 h60
  text "Symbol" at 3388.01,4243.07 h72
  text "Count" at 3669.91,4243.07 h72
  text "Hole Size" at 3912.52,4243.07 h72
  text "Hole Length" at 4430.47,4243.07 h72
  text "Plated" at 4842.77,4243.07 h72
  text "Drill Layer Pair" at 5090.24,4243.07 h72
  text "700" at 3669.91,4118.89 h60
  text "5.90mil (0.150mm)" at 3912.52,4118.89 h60
  text "-" at 4430.47,4118.89 h60
  text "PTH" at 4842.77,4118.89 h60
  text "TOP - L2-GND1" at 5090.24,4118.89 h60
  text "FOR 5.90 MIL DRILL +0/-5.90MIL" at 3460,3900 h60
  text "FAB_DWG" at -1322.95,-1032.44 h60

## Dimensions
3230,0 to 3230,2565 on Board Dimensions
0,2495 to 3300,2495 on Board Dimensions
70,70 to -130,-130 on Board Dimensions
